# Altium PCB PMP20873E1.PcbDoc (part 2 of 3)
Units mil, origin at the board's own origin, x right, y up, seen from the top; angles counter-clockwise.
Board outline 7700 x 3300 mil, 6 copper layers (Layer 1 - Top Layer, Layer 2 - Inner Signal 1, Layer 3 - Inner Signal 2, Layer 4 - Inner Signal 3, Layer 5 - Inner Signal 4, Layer 6 - Bottom Layer), stack 64 mil thick; 258 components, 121 nets, 676 pads, 168 vias.
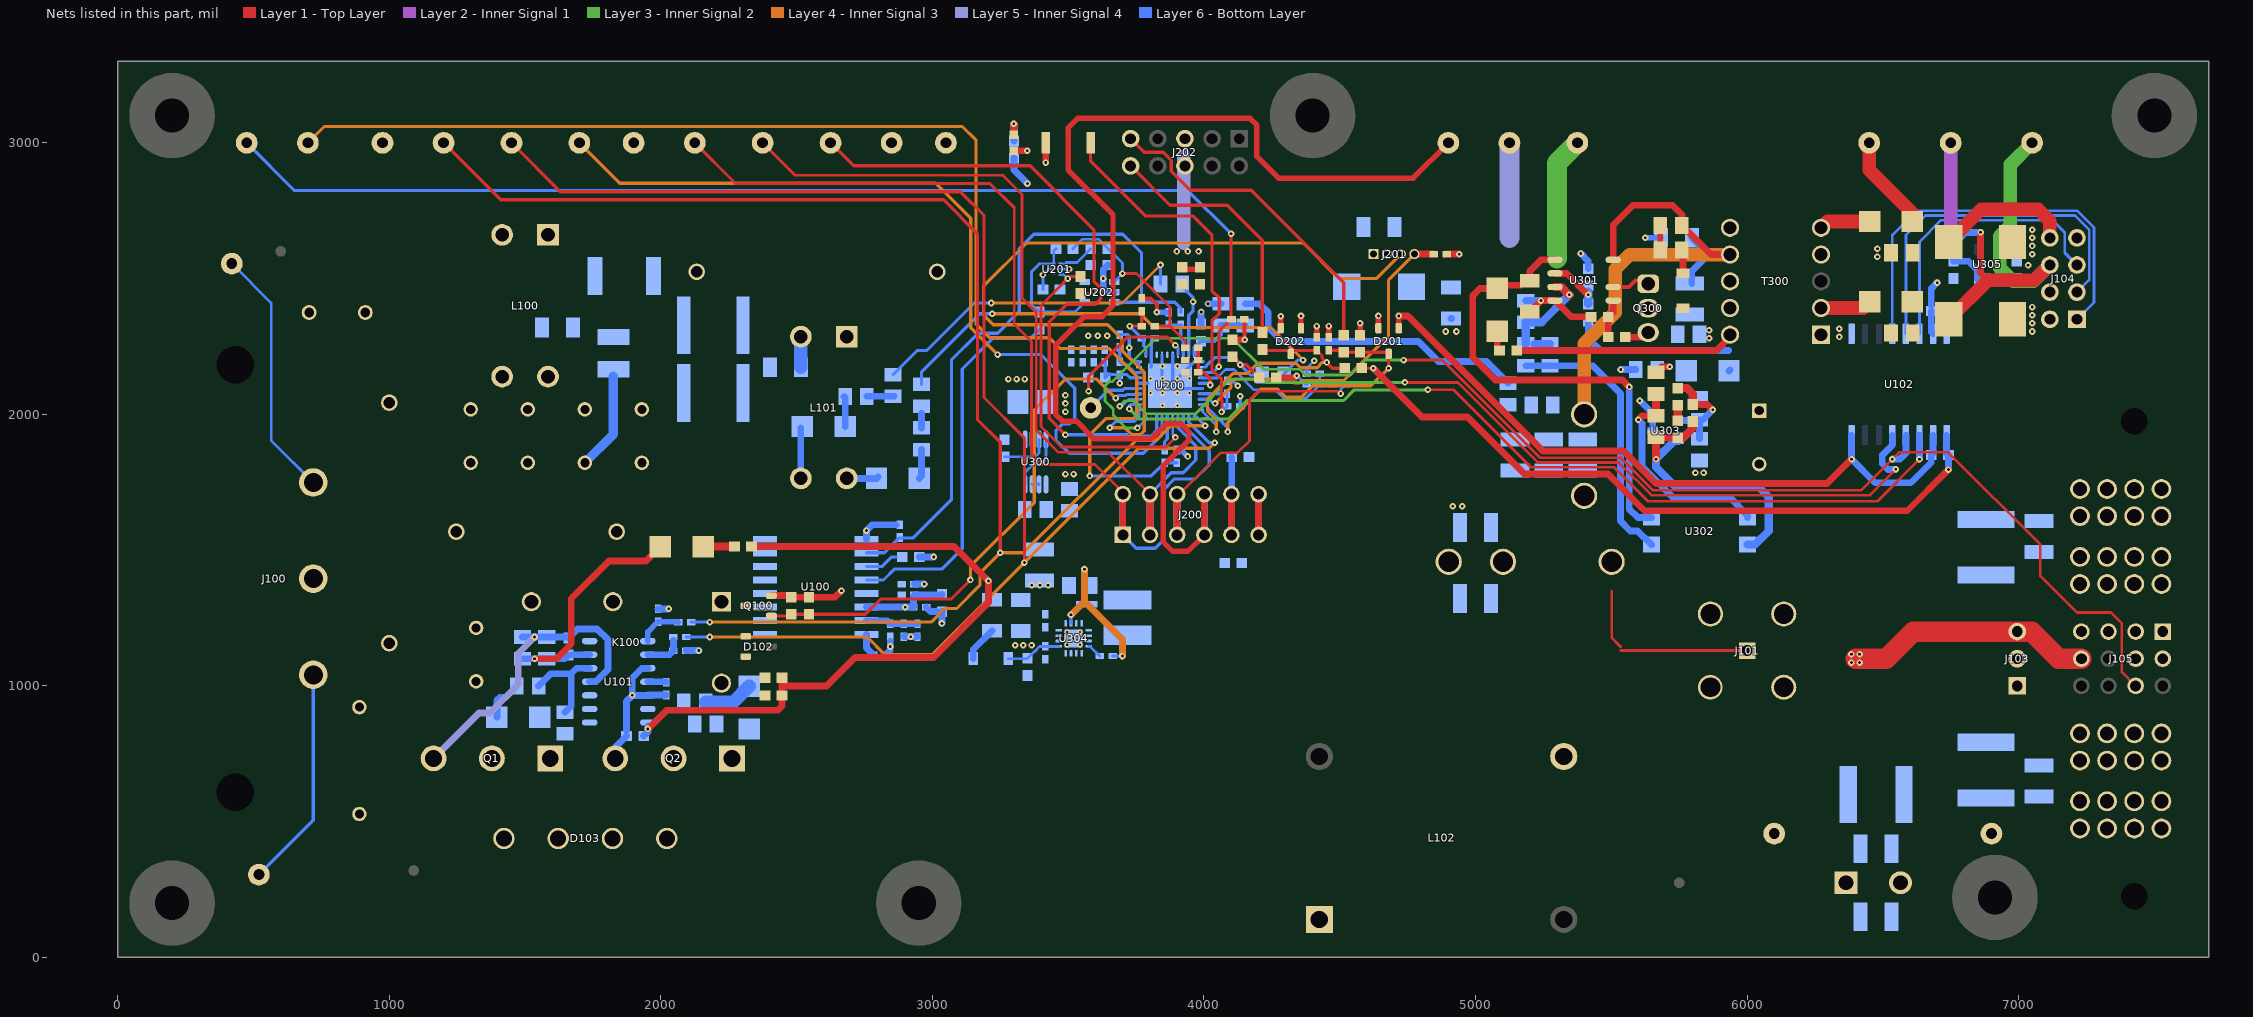
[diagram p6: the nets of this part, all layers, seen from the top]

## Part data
C100 C101 C104 C105: "CAP, CERM, 2200pF, 250V, +/-20%, KY, Radial D8x5mm"
C102: "CAP, Film, 0.47 µF, 275 V, +/- 20%, TH"
C103: library part ECQ-U2A474ML, "CAP, Film, 1uF, 275V, +/-20%, TH"
C107: "CAP, Film, 1 µF, 450 V, +/- 5%, TH"
C108 C109 C129 C130 C131 C132 C136 C137 C138: "CAP, CERM, 0.047 µF, 630 V, +/- 10%, X7R, 1210"
C110: library part DE1E3KX222MA4BL01, "CAP, CERM, 2200pF, 250V, +/-20%, E, Cap, 7x12x9 mm TH"
C111 C112: "CAP, CERM, 10uF, 16V, +/-20%, X5R, 0805"
C113 C126 C127 C222 C224 C320 C322: "CAP, CERM, 1uF, 25V, +/-10%, X7R, 0603"
C114 C122 C123: "CAP, CERM, 0.1uF, 6.3V, +/-10%, X7R, 0402"
C115: "CAP, CERM, 0.01uF, 50V, +/-10%, X7R, 0603"
C116: "CAP, CERM, 1000pF, 50V, +/-10%, X7R, 0603"
C117: "CAP, CERM, 1uF, 6.3V, +/-10%, X5R, 0603"
C118: "CAP, CERM, 0.022uF, 6.3V, +/-10%, X7R, 0402"
C119: "CAP, CERM, 1000pF, 50V, +/-10%, X7R, 0402"
C120 C121: "CAP, CERM, 1000pF, 6.3V, +/-10%, X5R, 0402"
C124 C125: "CAP, CERM, 0.056 µF, 250 V, +/- 10%, X7R, 2220"
C133 C134 C135: "CAP, CERM, 0.22 µF, 630 V, +/- 10%, X7R, 2220"
C188: "CAP, CERM, 1000pF, 16V, +/-10%, X7R, 0603"
C200 C203 C206 C219 C220: "CAP, CERM, 0.1uF, 6.3V, +/-10%, X5R, 0402"
C201: "CAP, CERM, 1000pF, 10V, +/-10%, X5R, 0402"
C202 C205: "CAP, CERM, 0.01uF, 6.3V, +/-10%, X7R, 0402"
C204: "CAP, CERM, 4700pF, 6.3V, +/-10%, X5R, 0402"
C207 C223: "CAP, CERM, 0.1 µF, 50 V, +/- 10%, X7R, 0603"
C208 C218: "CAP, CERM, 2.2uF, 10V, +/-10%, X5R, 0402"
C209 C210: library part Capacitor, "CAP, CER, 4.7UF, 6.3V, 20%, X5R, 0402"
C211 C212: "CAP, CERM, 2200 pF, 50 V, +/- 10%, X7R, 0603"
C213: "CAP, CERM, 1uF, 10V, +/-10%, X5R, 0402"
C214 C215: "CAP, CERM, 100pF, 50V, +/-5%, C0G/NP0, 0402"
C216 C217: "CAP, CERM, 1 µF, 25 V, +/- 10%, X7R, 0603"
C221: "CAP, TA, 100 µF, 16 V, +/- 10%, 0.1 ohm, SMD"
C288: "CAP, CERM, 2.2 µF, 25 V, +/- 10%, X5R, 1206"
C300: "CAP, CERM, 0.033 µF, 630 V, +/- 10%, X7R, 1210"
C301: "CAP, CERM, 1000 pF, 250 V, +/- 10%, X7R, 0805"
C303: "CAP, AL, 330 µF, 25 V, +/- 20%, 0.053 ohm, TH"
C304 C306 C323: "CAP, CERM, 3.3uF, 25V, +/-10%, X7R, 0805"
C305: "CAP, TA, 4.7uF, 10V, +/-10%, 3.4 ohm, SMD"
C307 C308: "CAP, CERM, 10 µF, 10 V, +/- 10%, X5R, 0805"
C309: "CAP, CERM, 0.047 µF, 50 V, +/- 10%, X7R, 0805"
C310: "CAP, CERM, 10 µF, 25 V, +/- 10%, X7R, 1206"
C311: "CAP, CERM, 68pF, 50V, +/-5%, C0G/NP0, 0603"
C312: "CAP, CERM, 1000pF, 50V, +/-10%, C0G/NP0, 0603"
C313: "CAP, CERM, 0.022uF, 25V, +/-10%, X7R, 0603"
C314 C321: "CAP, TA, 220 µF, 16 V, +/- 10%, 0.05 ohm, SMD"
C315 C326: "CAP, CERM, 22 µF, 16 V, +/- 20%, X5R, 1206"
C316 C317: "CAP, CERM, 0.1uF, 50V, +/-10%, C0G/NP0, 0402"
C318: "CAP, CERM, 10uF, 10V, +/-10%, X7R, 0805"
C319: "CAP, CERM, 2200pF, 25V, +10/%, X7R, 0402"
C324: "CAP, CERM, 47 µF, 6.3 V, +/- 20%, X5R, 1210"
D100 D101: "Diode, Fast Rectifier, 800 V, 1 A, SMA"
D102 D201 D202: "Diode, Schottky, 30V, 0.2A, SOT-23"
D103: "Diode, Switching-Bridge, 420V, 8A, TH"
D106: "Diode, Ultrafast, 600V, 1A, SMA"
D107 D108: "Diode, Schottky, 30 V, 1 A, SMA"
D300 D302 D304: library part 10BQ100TRPBF, "Diode, Schottky, 100V, 1A, SMB"
D301: library part US1M-13-F, "Diode, Ultrafast, 800V, 1A, SMA"
D303: "Diode, Ultrafast, 200 V, 1 A, SMA"
D305: "LED, Green, SMD"
D306: "Diode, Zener, 9.1 V, 500 mW, SOD-123"
F100: "Fuse, 15 A, 250 V, TH"
FID1 FID2 FID3: "Fiducial mark.  There is nothing to buy or mount."
H1 H2 H3 H4 H9 H11: "Machine Screw, Round, #4-40 x 1/4, Nylon, Philips panhead"
H5 H6 H7 H8 H10 H12: "Standoff, Hex, 0.5\"L #4-40 Nylon"
J100: "AC Receptacle, 10A 250VAC"
J101: "50 OHM BNC ELEVATED STRAIGHT JACK, TH"
J102: "Terminal Block, 2x1, 5.08mm, TH"
J103: "Header, 100mil, 3x1, Gold, TH"
J104: "Header, 100mil, 4x2, Gold, TH"
J105: "Signal Power Combo Socket Strip, 4x3, 4 Power Group, R/A, Gold, TH"
J106 J107 J203 J204 J205: library part 0312-0-15-15-34-27-10-0, "Pin Receptacle, .032-.046\" .075\" Dia, Gold, TH"
J200: "Receptacle, 2.54mm, 6x1, Gold, TH"
J201: "SOCKET .050\" GRID SIP 4 POS R/A, TH"
J202: "Header, 100mil, 5x2, Gold, TH"
K100: "Relay, SPST-NO (1 Form A), 10 A, 12 VDC, TH"
L100 L101: "Coupled inductor, 1.68 mH,  A,  ohm, TH"
L102: "Inductor, Toroid, Ferrite, 327 µH, 0.065 ohm, TH"
L103: "Inductor, Wirewound, 10 mH, 0.02 A, 32.8 ohm, SMD"
L104: "Inductor, Wirewound, Ferrite, 1.5 mH, 0.04 A, 37 ohm, SMD"
L300: "Inductor, Drum Core, Ferrite, 2.2 µH, 2.6 A, 0.047 ohm, SMD"
LBL1: library part THT-13-457-10, "Thermal Transfer Printable Labels, 1.250\" W x 0.250\" H - 10,000 per roll"
Logo2: library part Pb-Free
Logo3: library part FCC_disclaimer, "FCC_disclaimer"
LOGO4: library part IEC_HighVoltage, "IEC 61010-1 High Voltage Warning"
LOGO5: library part IEC_HotSurface, "IEC 61010-1 Hot Surface Warning"
NT200: "Single point connection between nets."
Q1 Q2: "MOSFET, N-CH, 500 V, 110 A, TO-247"
Q100: "MOSFET, N-CH, 60V, 0.26A, SOT-23"
Q300: "MOSFET, N-CH, 800V, 2.5A, IPAK"
R100 R101 R102 R103 R104 R105 R205 R209 R211: "RES, 348k ohm, 0.1%, 0.125W, 0805"
R106 R107: "RES, 51.1 ohm, 1%, 0.1W, 0603"
R108: "RES, 10.0k ohm, 1%, 0.1W, 0603"
R109 R110: "RES, 4.99 k, 1%, 0.125 W, 0805"
R112: "RES, 10.0k ohm, 1%, 0.063W, 0402"
R113: "RES, 12.7k ohm, 1%, 0.063W, 0402"
R114: "RES, 200 ohm, 1%, 0.1W, 0603"
R115: "RES, 5.49k ohm, 1%, 0.063W, 0402"
R116: "RES, 330k ohm, 5%, 0.063W, 0402"
R117 R118: "RES, 1.0k ohm, 5%, 0.063W, 0402"
R119 R120: "RES, 10.0, 1%, 0.125 W, 0805"
R121: "RES, 2.00 k, 1%, 0.25 W, 1206"
R122: "RES, 100, 1%, 0.25 W, 1206"
R202: "RES, 10.0 k, 1%, 0.1 W, 0402"
R203: "RES, 2.0k ohm, 5%, 0.063W, 0402"
R204: "RES, 3.3k ohm, 5%, 0.063W, 0402"
R206: "RES, 3.09 k, 0.1%, 0.062 W, AEC-Q200 Grade 0, 0402"
R207: "RES, 1.40k ohm, 1%, 0.063W, 0402"
R208 R218 R219 R220 R302: "RES, 2.0k ohm, 5%, 0.1W, 0603"
R212 R215: "RES, 10k ohm, 5%, 0.063W, 0402"
R213: "RES, 5.11k ohm, 0.1%, 0.125W, 0805"
R214: "RES, 1.00 ohm, 1%, 0.1W, 0603"
R216 R217: "RES, 5.11 k, 0.1%, 0.1 W, 0603"
R221 R223: "RES, 100 ohm, 5%, 0.1W, 0603"
R222: "RES, 221, 1%, 0.063 W, 0402"
R224: "RES, 10.0, 1%, 0.25 W, 1206"
R225: "RES, 1.00 k, 1%, 0.1 W, 0603"
R226: "RES, 4.87 k, 0.1%, 0.062 W, AEC-Q200 Grade 0, 0402"
R300: "RES, 300 k, 1%, 0.25 W, 1206"
R301: "RES, 200, 5%, 0.125 W, 0805"
R303: "RES, 100k ohm, 1%, 0.063W, 0402"
R304: "RES, 330 k, 0.1%, 0.1 W, 0603"
R305: "RES, 750, 0.5%, 0.1 W, 0603"
R307: "RES, 20.0, 1%, 0.1 W, 0603"
R308: "RES, 60.4k ohm, 1%, 0.1W, 0603"
R309: "RES, 3.01 k, 1%, 0.125 W, 0805"
R310: "RES, 22.1 k, 1%, 0.125 W, 0805"
R311 R315: "RES, 1.00k ohm, 1%, 0.1W, 0603"
R312: "RES, 21.5k ohm, 1%, 0.1W, 0603"
R313: "RES, 2.00 k, 1%, 0.125 W, 0805"
R314: "RES, 0.91, 1%, 0.25 W, 0805"
R316: "RES, 12.1 k, 1%, 0.125 W, 0805"
R317: "RES, 1.24 k, 1%, 0.125 W, 0805"
R318: "RES, 196 k, 1%, 0.125 W, 0805"
RT100: "Thermistor NTC, 50 ohm, 25%, D12.5xH16.5mm"
S200: "Switch, Push Button, SMD"
T300: "Transformer, 13 mH, TH"
TP100 TP109 TP300 TP301 TP302 TP303 TP304: library part 5000, "Test Point, Miniature, Red, TH"
TP102 TP103 TP108 TP205 TP206 TP212 TP305: library part 5001, "Test Point, Miniature, Black, TH"
TP200 TP201 TP202 TP203 TP204 TP207 TP208 TP209 TP210: library part 5002, "Test Point, Miniature, White, TH"
U100: "120 kHz Bandwidth, High-Voltage Isolation Current Sensor with Integrated Overcurrent Detection"
U101: "High-Speed,4A, 600V High-side Low-side Gate Driver Device, D0014A"
U102: "High-Performance, 8000 VPK Reinforced Triple Digital Isolator, DW0016B"
U200: "Highly Integrated Digital Controller for Isolated Power, RHA0040B"
U201: "SINGLE-POLE DOUBLE-THROW ANALOG SWITCH, DRY0006A"
U202: "Precision, Low Noise, Low Iq Operational Amplifier, 2.2 to 5.5 V, -40 to 125 degC, 5-pin SOT23 (DBV0005A), Green (RoHS & no Sb/Br)"
U300: "Micropower, 200 mA Ultra Low-Dropout Fixed or Adjustable Voltage Regulator, 8-pin Mini SOIC"
U301: "Constant-Voltage, Constant-Current Flyback Controller Using Opto-Coupler Feedback, D0007A"
U302: "Optocoupler, 5 kV, 50-600% CTR, TH-4"
U303: "Low Voltage Adjustable Precision Shunt Regulator, 39 ppm / degC, 15 mA, 0 to 70 degC, 3-pin SOT-23 (DBZ), Green (RoHS & no Sb/Br)"
U304: "Buck Step Down Regulator with 3 to 17 V Input and 5 V Output, -40 to 85 degC, 16-Pin QFN (RGT), Green (RoHS & no Sb/Br)"
U305: "Single Output LDO, 150 mA, Fixed 3.3 V Output, 2.5 to 24 V Input, with Ultra-Low IQ, 5-pin SOT-23 (DBV), -40 to 85 degC, Green (RoHS & no Sb/Br)"
ZZ1: library part AssemblyNoteLabel
ZZ2 ZZ3 ZZ4: library part AssemblyNote

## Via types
v1: diameter 24, hole 10, Layer 1 - Top Layer to Layer 6 - Bottom Layer, 148 vias
v2: diameter 19.68, hole 7.87, Layer 1 - Top Layer to Layer 6 - Bottom Layer, 12 vias
v3: diameter 19.68, hole 7.87, Layer 1 - Top Layer to Layer 6 - Bottom Layer, tented top, 5 vias
v4: diameter 20, hole 12, Layer 1 - Top Layer to Layer 6 - Bottom Layer, 2 vias
v5: diameter 90.55, hole 72.83, Layer 1 - Top Layer to Layer 6 - Bottom Layer, 1 vias

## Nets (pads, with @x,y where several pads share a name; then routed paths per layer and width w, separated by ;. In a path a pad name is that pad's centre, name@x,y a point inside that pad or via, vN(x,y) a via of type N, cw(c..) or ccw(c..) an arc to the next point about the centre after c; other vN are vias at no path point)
3V3: C117.1 C123.1 C126.2 C208.1 C209.1 C219.1 C222.2 C224.2 C305.1 D201.2 D202.2 J202.5 R112.2 R113.2 R116.1 R202.2 R214.2 R219.2 R220.2 R222.2 R304.2 R305.2 TP301.1 U100.14 U102.1 U200.27 U201.5 U202.5 U300.5 U300.6 | length 3564.5
  Layer 1 - Top Layer w10: R220.2@4581.5,2170 v1(4623,2170)
  Layer 1 - Top Layer w20: D202.2@4282.6,2307.4 v1@4282.6,2361 ; R219.2@4575,2291.5 v1(4575,2335) ; D201.2@4642.6,2307.4 v1(4642.6,2362.4)
  Layer 1 - Top Layer w25: v1(4623,2170) 4803,1990 4970,1990 5180,1780 5488.08,1780 5623.08,1645 6590,1645 v1(6741.5,1796.5)
  Layer 6 - Bottom Layer w10: U201.5@3470.31,2534.93 v1(3503.5,2534.93) ; R202.2@4379.38,2150 4379.38,2170.38 v1(4406,2197)
  Layer 6 - Bottom Layer w12: C209.1@3635,2191.38 3636.5,2189.88 R214.2@3636.5,2135 3647.87,2146.38 C208.1@3690,2146.38 ; v1(3690,2114) C208.1@3690,2146.38 ; U200.27@3760.83,2134.53 3728.47,2134.53 3716.62,2146.38 C208.1@3690,2146.38 ; R222.2@4133.62,2030 v1(4133.62,2066.38)
  Layer 6 - Bottom Layer w25: U100.14@2757.01,1290 C123.1@2930,1290 2930,1331.38 R116.1@2933.62,1335 3033.5,1335 C117.1@3035,1336.5 ; R112.2@2828.62,1115 2845,1131.38 2845,1164.63 ; R305.2@3300,2943.5 3300,2900 v1(3350,2850) ; U102.1@6735,1922.99 6735,1856.5 C126.2@6741.5,1850 v1(6741.5,1796.5)
  other v1: 2845,1145 2900,1290 3280,2130 3310,2130 3340,2130 4283,2361
3V3LLC: C127.2 C322.2 J104.4 U102.16 U305.1 | length 9.2
  Layer 6 - Bottom Layer w25: C127.2@6735,2373.5 C127.2@6741.5,2380
5V: C216.2 C307.1 C308.1 C317.1 C318.2 C324.1 J200.4 L300.2 R303.2 TP304.1 U300.4 U300.8 U304.14 | length 5105.2
  Layer 1 - Top Layer w20: J200.4@4001.3,1556.05 3941.03,1495.78 3885,1495.78 3850,1530.78 3850,1810 3945,1905 3945,1935 3915,1965 3860,1965 3805,1910 3595,1910 3530,1975 3478.5,1975 3453.5,2000 3453.5,2253.5 3560,2360 3625,2360 3665,2400 3665,2735 3500,2900 3500,3055 3535,3090 4170,3090 4195,3065 4195,2950 4275,2870 4770,2870 TP304.1@4900,3000
  Layer 1 - Top Layer w25: J200.4@4001.3,1556.05 J200.4@4001.3,1706.05
  Layer 4 - Inner Signal 3 w25: v1(3510.31,1261.69) 3560,1311.37 ; v1(3560,1430) 3560,1311.37 ; v1(3700,1110) 3700,1171.37 3560,1311.37
  Layer 6 - Bottom Layer w10: U300.4@3341.61,1742.32 3341.61,1786.61 3370,1815 3400,1815 3418.39,1833.39 U300.8@3418.39,1907.68 ; U304.14@3510.31,1230 v1(3510.31,1261.69) ; R303.2@3663.62,1110 v1(3700,1110)
  Layer 6 - Bottom Layer w25: J200.4@4001.3,1556.05 J200.4@4001.3,1706.05
7VLLC: C304.1 C314.1 C320.2 D304.1 J104.6 TP302.1 U305.3 | length 1696.5
  Layer 1 - Top Layer w25: v1(6860,2670) 6860,2520.87 6886.87,2494
  Layer 1 - Top Layer w50: C314.1@6742.87,2350 6886.87,2494 7059,2494 J104.6@7115,2550
  Layer 3 - Inner Signal 2 w50: TP302.1@7050,3000 6970,2920 6970,2695 6930,2655 6930,2540 6980,2490 7055,2490 J104.6@7115,2550
  Layer 6 - Bottom Layer w25: U305.3@6847.6,2498.87 6847.6,2532.4 6816.5,2563.5 C320.2@6760,2563.5 6760,2625 6805,2670 v1(6860,2670)
10VLLC: C306.1 C321.1 D302.1 J104.8 TP303.1 | length 857.4
  Layer 1 - Top Layer w50: TP303.1@6450,3000 6450,2900 6608.74,2741.26 D302.1@6608.74,2710 ; C321.1@6742.87,2635 6862.87,2755 7072,2755 7115,2712 J104.8@7115,2650
12V: C115.1 C217.2 C303.1 C315.1 C316.1 C323.1 C326.1 D300.1 D306.1 J103.3 J105.8 J200.5 R106.2 R107.2 R114.2 R224.2 R309.2 R316.2 TP300.1 U101.7 U304.10 U304.11 U304.12 U304.13 | length 4567.8
  Layer 1 - Top Layer w25: v1(1952.28,841.37) 2020.91,910 2430,910 2446.5,926.5 R106.2@2446.5,965 2446.5,1000 ; R114.2@2333.99,1513 3079.99,1513 v1(3206.5,1386.5) 3206.5,1306.5 3005,1105 2715,1105 2610,1000 2446.5,1000 ; R107.2@2446.5,1030 2446.5,1000 ; J200.5@4101.3,1556.05 J200.5@4101.3,1706.05 ; R309.2@5665,2155 5685,2175 v1(5715,2175)
  Layer 1 - Top Layer w75: 6400.26,1100 6512.52,1100 6612.52,1200 J103.3@6995,1200 7048.03,1200 7148.03,1100 J105.8@7231,1100
  Layer 3 - Inner Signal 2 w75: 5300,2575 5300,2925 TP300.1@5375,3000
  Layer 6 - Bottom Layer w25: C115.1@1936.5,815 1952.28,830.79 v1(1952.28,841.37) v1@1952.28,851.96 ; D306.1@3150.53,1100 3150.53,1133.44 C326.1@3220,1202.91 ; J200.5@4101.3,1556.05 J200.5@4101.3,1706.05 4102.6,1707.35 C217.2@4102.6,1843.35 ; R224.2@4910,2352.91 R224.2@4912,2352.91
  other v1: 6384.26,1086 6414.26,1086 6384.26,1116 6414.26,1116 3305,1150 3335,1150 3365,1150 4890,2305 4930,2305
+BRDG_N: R109.2 R119.2 U101.12 | length 366.2
  Layer 6 - Bottom Layer w25: R119.2@1550,1000 1595,1045 1670,1045 ; R109.2@1647,903 1670,926 1670,1045 ; U101.12@1737.72,1065 1690,1065 1670,1045
+BRDG_P: R110.2 R120.2 U101.6
-BRDG_N: C111.2 C112.2 C113.1 D103.3 Q1.3 Q2.2 U100.1 U100.2 U100.3 U100.4 U101.11 | length 1167.2
  Layer 5 - Inner Signal 4 w25: Q1.3@1163,733 1330,900 1370,900 1475,1005 1475,1120 v1(1535,1180)
  Layer 6 - Bottom Layer w25: C111.2@1490,1180 v1(1535,1180) C112.2@1580,1180 1656.5,1180 C113.1@1660,1176.5 1693.5,1210 1765,1210 1805,1170 1805,1060.21 1759.79,1015 U101.11@1737.72,1015
"\RECTIFIER SHTDWN": C122.1 U101.4 | length 68.3
  Layer 6 - Bottom Layer w25: U101.4@1952.28,1015 2018.62,1015 C122.1@2020,1013.62
AC_CUR_FAULT: C118.2 R116.2 U100.13
AC_CUR_SENSE: R225.1 U100.12 | length 1408.3
  Layer 6 - Bottom Layer w12: U100.12@2757.01,1390 2820,1390 2860,1430 3035,1430 3110,1505 3110,2167 3222.5,2279.5 3248.08,2279.5 3248.58,2280 3361.5,2280 R225.1@3395,2313.5
AC_CUR_VREF: C121.1 R212.2 U100.10 U202.3 | length 2415.7
  Layer 6 - Bottom Layer w12: U100.10@2757.01,1490 2823.62,1490 2878.62,1545 2930,1545 3070,1685 3070,2200 3169,2299 3240,2299 3320,2379 3320,2610 3373.5,2663.5 3701.5,2663.5 3770,2595 3770,2412.6 ; U202.3@3669.13,2412.6 3770,2412.6 ; R212.2@3915,2376.34 3915,2390 3892.4,2412.6 3770,2412.6
AC_DROP: TP210.1 U200.25 | length 207.3
  Layer 6 - Bottom Layer w12: TP210.1@3583,2024 3647.5,2088.5 3700.56,2088.5 3707.22,2095.16 U200.25@3760.83,2095.16
AC_L: C107.1 D103.2 K100.3 L102.1 RT100.2
AC_N: C105.2 C107.2 D101.2 L101.3 U100.5 U100.6 U100.7 U100.8 | length 185.2
  Layer 6 - Bottom Layer w25: L101.3@2515.5,1764 D101.2@2515.5,1949.24
ACL_SENSE: C212.1 R102.1 R217.2 U200.2 | length 399.1
  Layer 1 - Top Layer w12: C212.1@4105,2223.5 C212.1@4105,2212 v1(4134,2183) 4155.5,2183 R217.2@4203.5,2135
  Layer 6 - Bottom Layer w12: 4003.08,2174.08 4005.08,2174.08 4016.5,2185.51 4016.5,2186.5 4039,2209 4111,2209 v1@4135,2185 ; v1@4133,2182 4170,2145 R102.1@4215,2145 ; v1@4133,2183 v1@4133,2186
ACN_SENSE: C211.1 R105.1 R216.2 U200.39 | length 298.2
  Layer 6 - Bottom Layer w12: R105.1@3910,2490 3910,2480 3960,2430 v1(3960,2415) 3960,2381.1 3943.9,2365 U200.39@3943.9,2219.17
AGND: C114.2 C116.2 C117.2 C118.1 C121.2 C123.2 C126.1 C200.1 C201.2 C202.1 C203.2 C204.2 C205.2 C206.1 C207.2 C209.2 C210.2 C211.2 C212.2 C213.2 C214.2 C215.2 C218.2 C219.2 C220.2 C222.1 C223.2 C224.1 C305.2 C307.2 C308.2 D201.1 D202.1 D305.2 J202.6 NT200.2 R115.1 R213.1 R216.1 R217.1 R226.1 S200.2 TP205.1 TP206.1 TP212.1 U100.9 U102.2 U102.8 U200.1 U200.6 U200.26 U200.29 U200.30 U200.32 U200.34 U200.36 U200.41 U201.2 U202.2 U300.1 | length 5238.4
  Layer 1 - Top Layer w10: C223.2@3544.93,2444.82 3584.44,2444.82 v1(3592.31,2452.69)
  Layer 1 - Top Layer w15: R226.1@3771.38,2427.24 3802.76,2427.24 3826.38,2403.62 v1(3826.38,2376.34) ; v1@4148.62,2276.36 C200.1@4148.62,2350
  Layer 1 - Top Layer w20: R216.1@3920,2550 3936.38,2533.62 C211.2@3985,2533.62 ; D202.1@4357.4,2307.4 v1(4357.4,2362.4) ; C214.2@4415,2283.62 v1(4415,2325) ; C215.2@4460,2283.62 v1(4460,2325) ; D201.1@4717.4,2307.4 D201.1@4717.4,2317.24 v1(4717.4,2362.4)
  Layer 1 - Top Layer w25: D305.2@3300,2970.47 v1(3349.53,2970.47) ; v1(3417.32,2927.32) S200.2@3417.32,3000 ; C212.2@4105,2274.99 v1(4150,2275) ; R217.1@4266.5,2135 4335.29,2135 v1@4341.79,2141.5 ; v1(4717.4,2362.4) 4750.64,2362.4 5248.04,1865 5545,1865 5665,1745 6295,1745 v1(6385,1835)
  Layer 5 - Inner Signal 4 w50: 3925,2630 3925,2950
  Layer 6 - Bottom Layer w10: C222.1@3407.01,2460 v1(3407.01,2513.44) 3428.5,2534.93 3439.79,2534.93 ; v1(4342,2142) 4374,2110 C201.2@4379.38,2110
  Layer 6 - Bottom Layer w12: C213.2@3690,2293.62 3719.38,2293.62 3725,2288 3725,2210 3741.42,2193.58 U200.30@3760.83,2193.58 U200.29@3760.83,2176 ; U200.26@3755,2114.84 U200.41@3794.29,2114.84 ; U200.41@3806.1,2173.9 U200.32@3806.1,2219.17 3806.1,2267.48 C204.2@3818.62,2280 ; U200.41@3845.47,2134.53 U200.34@3845.47,2219.17 ; U200.41@3875,2105 U200.41@3884.84,2114.84 ; U200.41@3884.84,2095.16 U200.6@3995,2095.16 ; U200.36@3884.84,2219.17 U200.41@3884.84,2114.84 ; U200.1@3997,2193.58 3963.58,2193.58 U200.41@3884.84,2114.84 ; C218.2@4085,2123.62 4106.38,2123.62 v1(4125,2105)
  Layer 6 - Bottom Layer w20: v1(3826.38,2376.34) C206.1@3870,2376.34 ; C202.1@3900,1868.62 3903.62,1865 3920,1865 v1(3940,1845)
  Layer 6 - Bottom Layer w25: U100.9@2757.01,1540 v1(2757.01,1572.01) 2778.62,1593.62 2867.19,1593.62 ; R115.1@2895,1181.38 C114.2@2945,1181.38 ; C118.1@2933.62,1375 v1(2970,1375) ; C116.2@2951.5,1475 v1(3005,1475) ; C123.2@2977.24,1290 2993.74,1273.5 3015.3,1273.5 ; v1(3035,1230) C117.2@3035,1273.5 ; C224.1@3646.5,2550 3629.45,2532.95 3629.45,2465.55 3645,2450 U202.2@3669.13,2450 ; C207.2@3989,2332.5 3989,2376 v4(3990,2377) ; v4(4015,2407) R213.1@4063,2407 ; U102.8@6385,1922.99 v1(6385,1835) 6471.97,1748.03 6603.03,1748.03 6678.5,1823.5 C126.1@6678.5,1850 6685,1856.5 U102.2@6685,1922.99
  other v1: 2920,1181.38 3490,1780 3520,1780 3490,2010 3490,2040 3490,2070 3725,2245 3574,2289 3609,2289 3644,2289 3629.45,2500 3900,2600 3940,2600 3980,2600
  other v2: 3848.03,2033.15 3901.97,2033.15 3803.15,2078.03 3848.03,2078.03 3901.97,2078.03 3946.85,2078.03 3803.15,2131.97 3848.03,2131.97 3901.97,2131.97 3946.85,2131.97 3848.03,2176.85 3901.97,2176.85
CT1: T300.8
EAP1: U200.33
EAP2: U200.35
EARTH: C100.2 C101.2 C104.1 C105.1 C110.1 J100.3
FAN_CTRL: J201.4 R215.2 U200.8 | length 1239.4
  Layer 1 - Top Layer w25: J201.4@4775,2590 R215.2@4846.38,2590
  Layer 4 - Inner Signal 3 w12: v1(4041,2040) 4099.5,2098.5 4099.5,2115.56 4114.44,2130.5 4317.44,2130.5 4331.44,2116.5 4352.56,2116.5 4360.56,2124.5 4514.5,2124.5 4680,2290 4680,2495 J201.4@4775,2590
  Layer 6 - Bottom Layer w12: U200.8@3983,2055.79 4019.21,2055.79 4035,2040 v1(4041,2040)
FAN_FB: J201.3 U200.21 | length 3013
  Layer 4 - Inner Signal 3 w12: v1(3653,1951) 3708.5,1951 3735,1924.5 3765.56,1924.5 3780.5,1939.44 3780.5,2067.67 3779.81,2068.36 3779.81,2154.13 3699.5,2234.44 3699.5,2275.5 3645,2330 3223.94,2330 3188,2365.94 3188,2472 3347,2631 4365,2631 4496,2500 4635,2500 J201.3@4725,2590
  Layer 6 - Bottom Layer w12: v1@3651.24,1951 v1(3653,1951) 3675.62,1973.62 3742.56,1973.62 3744.44,1975.5 3745.5,1975.5 3760.83,1990.83 U200.21@3760.83,2014
G_AC_I: C223.1 U200.15 U201.6 | length 1290.6
  Layer 1 - Top Layer w10: C223.1@3544.93,2507.81 3506.38,2507.81 v1(3498.5,2499.93) 3400.01,2401.44 3400.01,1954.99 3475,1880 3860,1880 v1(3895,1915)
  Layer 6 - Bottom Layer w10: U201.6@3470.31,2515.25 3483.19,2515.25 v1(3498.5,2499.93) ; U200.15@3884.84,1990.83 3884.84,1925.16 v1(3895,1915)
GAN_FAULT: C201.1 R202.1 R203.1 U200.4 | length 601.6
  Layer 6 - Bottom Layer w10: U200.4@3989.17,2134.53 3989.7,2134 4048.65,2134 4079.65,2165 4110,2165 4185,2090 4264,2090 4293,2061 4377.62,2061 C201.1@4426.62,2110 ; R202.1@4426.62,2150 C201.1@4426.62,2110 ; R203.1@4474.38,2110 C201.1@4426.62,2110
HS_GATE1: J200.1 TP202.1 U200.13 | length 3704.8
  Layer 1 - Top Layer w10: 3301,2760 3301,2332 3365.01,2267.99 3365.01,1854.99 3405,1815 3599,1815 3701.3,1712.7 J200.1@3701.3,1706.05
  Layer 1 - Top Layer w12: TP202.1@2125,3000 2275,2850 3211,2850 3301,2760
  Layer 1 - Top Layer w25: J200.1@3701.3,1556.05 J200.1@3701.3,1706.05
  Layer 6 - Bottom Layer w12: J200.1@3701.3,1556.05 3750.3,1507.05 3820,1507.05 3850,1537.05 3850,1720.78 3891,1761.78 3967,1761.78 4020,1814.78 4020,1865 3924.21,1960.79 U200.13@3924.21,1997
  Layer 6 - Bottom Layer w25: J200.1@3701.3,1556.05 J200.1@3701.3,1706.05
HS_GATE2: TP209.1 U200.17 | length 3179.6
  Layer 4 - Inner Signal 3 w12: TP209.1@1700,3000 1849,2851 3012,2851 3141.5,2721.5 3141.5,2318.5 v1(3240,2220)
  Layer 6 - Bottom Layer w12: v1(3240,2220) 3400,2220 3524,2096 3524,1984 3505,1965 3480,1965 3455,1940 3455,1905 3503.74,1856.26 3776.26,1856.26 3845.47,1925.47 U200.17@3845.47,1990.83 U200.17@3845.47,1997
HVBUS: C108.1 C109.1 C129.1 C130.1 C131.1 C132.1 C133.2 C134.1 C135.2 C136.1 C137.1 C138.1 C300.1 C301.1 D103.1 J102.1 J105.P1 J105.P4 J106.1 J204.1 Q1.2 R205.2 R300.2 T300.7 TP100.1 U301.8 | length 1980.3
  Layer 1 - Top Layer w25: U301.8@5507.28,2569 5507.28,2697.28 5580,2770 5725,2770 5760,2735 5760,2727.5 ; C301.1@5760,2695 5866.57,2588.43 T300.7@5937.48,2588.43
  Layer 4 - Inner Signal 3 w50: J106.1@5400,2000 5400,2260 5515,2375 5515,2535 5568.43,2588.43 T300.7@5937.48,2588.43
  Layer 6 - Bottom Layer w25: C300.1@5796,2482.09 5796,2526 5858.43,2588.43 5858.66,2588.43 ; R300.2@5797.09,2650 5858.66,2588.43 ; T300.7@5937.48,2588.43 5858.66,2588.43
LLC_AGND: C127.1 C304.2 C306.2 C314.2 C320.1 C321.2 C322.1 J104.2 J104.7 T300.1 T300.4 TP305.1 U102.9 U102.15 U305.2 | length 479.9
  Layer 2 - Inner Signal 1 w50: 6750,2700 TP305.1@6750,3000
  Layer 6 - Bottom Layer w25: C127.1@6678.5,2380 6678.5,2303.5 U102.15@6685,2297.01 ; 6678.5,2399.7 6678.5,2463.5 v1(6700,2485)
  other v1: 6340,2285 7050,2305 6340,2315 7050,2335 7050,2365 7050,2395 7035,2548.72 6480,2580 7050,2590 6480,2610 7050,2620 7050,2650 7050,2680
LS_GATE1: J200.2 TP204.1 U200.14 | length 3152.8
  Layer 1 - Top Layer w10: TP204.1@2375,3000 2495,2880 3260,2880 3330,2810 3330,2427.51 3382.51,2375 3382.51,1942.49 3465,1860 3647.35,1860 J200.2@3801.3,1706.05
  Layer 1 - Top Layer w25: J200.2@3801.3,1556.05 J200.2@3801.3,1706.05
  Layer 6 - Bottom Layer w12: J200.2@3801.3,1706.05 3880.03,1784.78 3923,1784.78 3970,1831.78 3970,1885 3904.53,1950.47 U200.14@3904.53,1997
  Layer 6 - Bottom Layer w25: J200.2@3801.3,1556.05 J200.2@3801.3,1706.05
LS_GATE2: TP207.1 U200.18 | length 2436.8
  Layer 1 - Top Layer w12: TP207.1@2625,3000 2710,2915 3360,2915 3595,2680 3595,2490 3620,2465 3620,2425 3600,2405 3495,2405 3430,2340 3430,1985 v1(3490,1925)
  Layer 6 - Bottom Layer w12: v1(3490,1925) 3713.62,1925 3715,1926.38 3721.38,1920 3805,1920 3825.79,1940.79 U200.18@3825.79,1997
NCD1: U101.8
NCD2: U101.9
NCD3: U101.10
NCD4: U101.14
NetC100_1: C100.1 C103.1 L100.3 L101.1 L103.2 R121.1
NetC101_1: C101.1 D100.2 K100.2 L101.4 L104.2 RT100.1 | length 480.8
  Layer 6 - Bottom Layer w25: L101.4@2684.5,1764 D100.2@2794,1764 D100.2@2800,1770
  Layer 6 - Bottom Layer w35: C101.1@1720,1821.57 1825,1926.57 L104.2@1825,2140.94
NetC102_1: C102.1 F100.2 L100.2
NetC102_2: C102.2 J100.2 L100.1 TP108.1 | length 818.9
  Layer 6 - Bottom Layer w12: TP108.1@519.76,304.76 720,505 J100.2@720,1040.67
NetC103_2: C103.2 C104.2 L100.4 L101.2 R122.1 | length 112.6
  Layer 6 - Bottom Layer w50: R122.1@2515.5,2173.41 L101.2@2515.5,2286
NetC111_1: C111.1 C112.1 C113.2 D106.1 U101.13 | length 985.5
  Layer 1 - Top Layer w25: v1(1535,1100) 1615,1100 1670,1155 1670,1321 1809,1460 1945.26,1460 D106.1@1998.26,1513
  Layer 6 - Bottom Layer w25: C111.1@1490,1100 v1(1535,1100) C112.1@1580,1100 1646.5,1100 C113.2@1660,1113.5 1661.5,1115 U101.13@1737.72,1115
NetC114_1: C114.1 R113.1 R115.2 U100.15 | length 192.7
  Layer 6 - Bottom Layer w25: U100.15@2757.01,1240 2833.62,1240 R113.1@2845,1228.62 R115.2@2895,1228.62 C114.1@2945,1228.62
NetC116_1: C116.1 U100.11 | length 125.3
  Layer 6 - Bottom Layer w12: U100.11@2757.01,1440 2815,1440 2850,1475 2867.82,1475
NetC119_1: C119.1 R117.1 U101.1 | length 161.6
  Layer 6 - Bottom Layer w20: U101.1@1952.28,1165 1952.28,1198.66 C119.1@1990,1236.38 2062.62,1236.38 R117.1@2064,1235
NetC120_1: C120.1 R118.1 U101.2 | length 137.5
  Layer 6 - Bottom Layer w25: U101.2@1952.28,1115 2031.38,1115 C120.1@2046.38,1130 2046.38,1167.19
NetC124_1: C124.1 C125.1 L103.1
NetC124_2: C124.2 C125.2 R122.2
NetC202_2: C202.2 R204.2 TP203.1 | length 4695.4
  Layer 4 - Inner Signal 3 w12: TP203.1@700,3000 760,3060 3110,3060 3161,3009 3161,2332 3211,2282 3431,2282 3471,2242 3652,2242 3753,2141 3753,1997 3741,1985 3640,1985 3579,1924 v1(3579,1773)
  Layer 6 - Bottom Layer w12: v1(3579,1773) 3806.62,1773 R204.2@3855,1821.38 C202.2@3900,1821.38
NetC203_1: C203.1 C205.1 R207.1 U200.5 | length 214.7
  Layer 1 - Top Layer w12: R207.1@3978.62,2245 C205.1@3978.62,2200 C203.1@3978.62,2155 3999,2155 4023,2131 v1(4023,2108) v1@4020,2111
  Layer 6 - Bottom Layer w12: U200.5@3983,2114.84 U200.5@3989.17,2114.84 4017.16,2114.84 v1@4023.5,2108.5
NetC204_1: C204.1 R206.2 R226.2 U200.31 | length 238.8
  Layer 1 - Top Layer w12: v1(3726.38,2325) R206.2@3771.38,2325 R226.2@3771.38,2380 R226.2@3770,2381.38
  Layer 6 - Bottom Layer w12: v1(3726.38,2325) C204.1@3771.38,2280 3778,2273.38 3778,2253 3786.42,2244.58 U200.31@3786.42,2213
NetC206_2: C206.2 R212.1 U200.38 | length 162.4
  Layer 6 - Bottom Layer w12: C206.2@3870,2329.1 R212.1@3915,2329.1 ; R212.1@3918.62,2329.1 R212.1@3915,2329.1 ; U200.38@3924.21,2219.17 3924.21,2270.79 3915,2280 R212.1@3915,2329.1
NetC208_2: C208.2 C213.1 U200.28 | length 148.1
  Layer 6 - Bottom Layer w12: C213.1@3690,2248.37 C213.1@3690,2246.38 C208.2@3690,2193.62 3698.62,2185 3713,2185 3743.79,2154.21 U200.28@3767,2154.21
NetC210_1: C210.1 C220.1 R214.1 U200.37 | length 537.3
  Layer 1 - Top Layer w12: v1(3575,2085) 3575,2140 3720,2285 3864,2285 v1(3895,2254)
  Layer 6 - Bottom Layer w12: R214.1@3573.5,2135 3575,2133.5 v1(3575,2085) ; v1(3895,2254) 3904.53,2244.47 U200.37@3904.53,2219.17
NetC221_1: C221.1 C288.2 J201.2 R224.1
NetC301_2: C301.2 R300.1 R301.2 | length 152.9
  Layer 1 - Top Layer w20: R301.2@5680,2605 C301.2@5680,2695 C301.2@5680,2700
  Layer 6 - Bottom Layer w20: v1(5625,2650) R300.1@5682.91,2650
NetC309_1: C309.1 R318.2 U302.3 | length 1010.7
  Layer 6 - Bottom Layer w25: R318.2@5185,2179 C309.1@5275,2179 5431,2179 5533.5,2076.5 5533.5,1607.28 5569.92,1570.87 5596.97,1570.87 U302.3@5647.83,1520
NetC309_2: C309.2 R310.2 R318.1 U301.3 | length 403.6
  Layer 1 - Top Layer w30: U301.3@5292.72,2469 5316,2469 v1(5345,2440)
  Layer 6 - Bottom Layer w30: R318.1@5185,2259 R310.2@5185,2339 5244,2339 v1(5345,2440) ; 5217.5,2259 C309.2@5275,2259
NetC311_1: C311.1 R311.1 U301.5 | length 143.7
  Layer 1 - Top Layer w25: R311.1@5489.5,2284 R311.1@5488.5,2285.01 C311.1@5488.5,2359 5507.9,2378.41 5507.28,2379.03 U301.5@5507.28,2419
NetC312_1: C312.1 C313.1 R316.1 R317.2 U303.1 | length 376
  Layer 1 - Top Layer w25: C313.1@5800,2036.5 5853.5,2036.5 v1(5873.5,2016.5)
  Layer 1 - Top Layer w30: C312.1@5745,2096.5 5778.5,2096.5 5800,2075 5800,2057.18
  Layer 6 - Bottom Layer w25: U303.1@5747.24,1977.4 5822.4,1977.4 R316.1@5825,1974.8 ; R317.2@5825,1910 R316.1@5825,1974.8 ; v1(5873.5,2016.5) 5837.01,1980 R316.1@5825,1980 R316.1@5825,1974.8
NetC312_2: C312.2 R315.2 | length 36.3
  Layer 1 - Top Layer w30: R315.2@5745,1976.5 5745,2012.82
NetC313_2: C313.2 R313.1 R315.1 U302.2 U303.2 | length 1057.9
  Layer 1 - Top Layer w30: v1(5665,1835) R313.1@5665,1915 5743.5,1915 R315.1@5745,1913.5 5763.5,1913.5 5800,1950 5800,1952.82
  Layer 6 - Bottom Layer w30: U303.2@5747.24,1902.6 5732.6,1902.6 v1(5665,1835) 5665,1805 5735,1735 6040,1735 6080,1695 6080,1570 6030,1520 U302.2@6002.17,1520
NetC319_1: C319.1 D306.2 R302.1 U304.9 | length 204.4
  Layer 6 - Bottom Layer w10: D306.2@3279.47,1100 3348.5,1100 R302.1@3350,1101.5 3374,1125.5 3375.15,1125.5 3395,1145.35 C319.1@3415.65,1145.35 U304.9@3465.04,1145.35
NetD100_1: D100.1 R100.2 | length 109.5
  Layer 6 - Bottom Layer w25: D100.1@2951.48,1764 2960,1772.52 R100.2@2960,1870
NetD101_1: D101.1 R103.2 | length 111.5
  Layer 6 - Bottom Layer w25: R103.2@2675,2065 2678.74,2061.26 D101.1@2678.74,1955
NetD102_1: D102.1 K100.1 Q100.3
NetD102_2: D102.2 K100.5 R106.1 R107.1
NetD106_2: D106.2 R114.1 | length 115.3
  Layer 1 - Top Layer w30: D106.2@2155.74,1513 R114.1@2271,1513
NetD107_1: D107.1 R119.1 | length 157.8
  Layer 6 - Bottom Layer w25: D107.1@1396.26,885 1396.26,947.26 1407,958 1428,958 R119.1@1470,1000
NetD107_2: D107.2 Q1.1 R109.1
NetD108_1: D108.1 R120.1 | length 184.3
  Layer 6 - Bottom Layer w50: R120.1@2165,940 2266.26,940 D108.1@2325,998.74
NetD108_2: D108.2 Q2.1 R110.1
NetD300_2: D300.2 R307.2 R308.2 T300.10 | length 1412.2
  Layer 1 - Top Layer w25: R307.2@5151.5,2235 5886.87,2235 T300.10@5937.48,2285.61
  Layer 6 - Bottom Layer w25: R308.2@5415,2343.5 5415,2280 5460,2235 5932.78,2235 ; D300.2@5933.74,2160 D300.2@5937.48,2163.74
NetD301_1: D301.1 R301.1 | length 68.2
  Layer 1 - Top Layer w25: R301.1@5760,2605 5764,2601 5764,2538.48
NetD301_2: D301.2 Q300.2 T300.9
NetD302_2: D302.2 T300.5 | length 148
  Layer 1 - Top Layer w50: T300.5@6272.52,2686.85 6295.67,2710 6410.89,2710
NetD303_2: D303.2 R307.1 | length 74.8
  Layer 1 - Top Layer w25: D303.2@5080,2306.26 5080,2243.5 R307.1@5088.5,2235
NetD304_2: D304.2 T300.2 | length 188.4
  Layer 1 - Top Layer w50: T300.2@6272.52,2391.57 6427.83,2391.57 D304.2@6451.26,2415
NetD305_1: D305.1 R305.1 | length 87.2
  Layer 1 - Top Layer w25: 3300,3046.28 v1(3300,3070)
  Layer 6 - Bottom Layer w25: R305.1@3300,3006.5 v1(3300,3070)
NetF100_1: F100.1 J100.1 TP109.1 | length 929.9
  Layer 6 - Bottom Layer w10: TP109.1@420,2555 565,2410 565,2210 565,1904.33 J100.1@720,1749.33
NetJ104_1: J104.1 U102.12 | length 1531.9
  Layer 6 - Bottom Layer w10: U102.12@6535,2297.01 6535,2660 6625,2750 7214.75,2750 7277.5,2687.25 7277.5,2412.5 J104.1@7215,2350
NetJ104_3: J104.3 U102.13 | length 1338.4
  Layer 6 - Bottom Layer w10: U102.13@6585,2297.01 6585,2660 6657.5,2732.5 7207.5,2732.5 7260,2680 7260,2495 J104.3@7215,2450
NetJ104_5: J104.5 U102.14 | length 1063.4
  Layer 6 - Bottom Layer w10: U102.14@6635,2297.01 6635,2635 6715,2715 7125,2715 7170,2670 7170,2595 J104.5@7215,2550
NetJ200_3: J200.3 R203.2 | length 1195.2
  Layer 1 - Top Layer w10: J200.3@3901.3,1697.78 4062.3,1858.78 4123.78,1858.78 4167.5,1902.5 4167.5,2052.5 4200,2085 4495,2085 v1(4503.62,2076.38)
  Layer 1 - Top Layer w25: J200.3@3901.3,1556.05 J200.3@3901.3,1706.05
  Layer 6 - Bottom Layer w10: v1(4503.62,2076.38) 4503.62,2092 R203.2@4521.62,2110
  Layer 6 - Bottom Layer w25: J200.3@3901.3,1556.05 J200.3@3901.3,1706.05
NetJ202_9: J202.9 R221.2 | length 1221.5
  Layer 1 - Top Layer w12: J202.9@3730,3015 3780,2965 3850,2965 3880,2935 3880,2895 3950,2825 4175,2825 4515,2485 R221.2@4515,2291.5
NetJ202_10: J202.10 R223.2 | length 937.4
  Layer 1 - Top Layer w12: J202.10@3730,2915 3875,2770 4085,2770 4214.57,2640.43 4214.57,2301.93 R223.2@4215,2301.5
NetL104_1: L104.1 R121.2
NetL300_1: L300.1 U304.1 U304.2 U304.3
NetQ300_1: Q300.1 U301.6 | length 138.6
  Layer 1 - Top Layer w15: U301.6@5507.28,2469 5564.9,2469 5588.85,2492.95 Q300.1@5636,2492.95
NetQ300_3: Q300.3 R311.2 R314.2 | length 83.5
  Layer 1 - Top Layer w25: R311.2@5552.5,2284 5635.95,2284 Q300.3@5636,2284.05
NetR100_1: R100.1 R101.2 | length 54
  Layer 6 - Bottom Layer w25: R100.1@2960,1950 2960,2004
NetR101_1: R101.1 R102.2 | length 1705.8
  Layer 4 - Inner Signal 3 w12: v1(3220,2370) 3765,2370 3815,2320 4245,2320 v1(4365,2200)
  Layer 6 - Bottom Layer w12: R101.1@2960,2110 2960,2156 3174,2370 v1(3220,2370) ; R102.2@4295,2145 4295,2150 4345,2200 v1(4365,2200)
NetR103_1: R103.1 R104.2 | length 100
  Layer 6 - Bottom Layer w25: R103.1@2758.74,2066.26 R104.2@2858.74,2066.26
NetR104_1: R104.1 R105.2 | length 1222.2
  Layer 4 - Inner Signal 3 w12: v1(3217,2410) 3700,2410 v1(3840,2550)
  Layer 6 - Bottom Layer w12: R104.1@2855,2146.26 2943.74,2235 2979.37,2235 3154.37,2410 v1(3217,2410) ; R105.2@3840,2480 v1(3840,2550)
NetR112_1: R112.1 U100.16 | length 85.1
  Layer 6 - Bottom Layer w25: U100.16@2757.01,1190 2757.01,1139.37 R112.1@2781.38,1115
NetR205_1: R205.1 R209.2
NetR206_1: R206.1 R207.2 R208.1 R218.1 U202.1 | length 770.8
  Layer 1 - Top Layer w10: v1(3700,2518.27) 3751.73,2518.27 3875,2395 3875,2325 ; R206.1@3818.62,2325 3875,2325 ; R207.2@3931.38,2245 3931.38,2268.62 3875,2325
  Layer 6 - Bottom Layer w10: R218.1@3517.99,2610 3552.99,2645 3611.5,2645 R208.1@3646.5,2610 3700,2556.5 v1(3700,2518.27) U202.1@3669.13,2487.4
NetR208_2: R208.2 U201.4 | length 136.1
  Layer 6 - Bottom Layer w10: U201.4@3470.31,2554.62 3488.54,2554.62 3493.36,2559.43 3532.94,2559.43 R208.2@3583.5,2610
NetR209_1: R209.1 R211.2 | length 1121.2
  Layer 6 - Bottom Layer w25: R211.2@4152,2407 4205,2407 4237,2375 4237,2320 4289,2268 4790,2268 4863,2195 5040,2195 R209.1@5120,2115
NetR218_2: R218.2 R225.2 U201.3 U202.4 | length 495.4
  Layer 6 - Bottom Layer w10: R218.2@3455,2610 3446.69,2601.69 U201.3@3446.69,2554.62 3394.62,2554.62 3365,2525 3365,2405 3393.5,2376.5 3445,2376.5 3524.76,2376.5 U202.4@3560.87,2412.6
NetR303_1: R303.1 U304.4 | length 55.7
  Layer 6 - Bottom Layer w10: U304.4@3575.28,1145.35 3581.02,1145.35 R303.1@3616.38,1110
NetR304_1: R304.1 U300.7 | length 183.6
  Layer 6 - Bottom Layer w10: R304.1@3265,1843.5 3378.5,1843.5 3392.8,1857.8 U300.7@3392.8,1907.68
NetR308_1: R308.1 R312.2 U301.2 | length 201.3
  Layer 1 - Top Layer w25: U301.2@5292.72,2519 5336,2519 v1(5415,2440)
  Layer 6 - Bottom Layer w30: R308.1@5415,2406.5 v1(5415,2440) 5415,2452.82
NetR309_1: R309.1 R313.2 U302.1 | length 768
  Layer 1 - Top Layer w25: v1(5600,1980) 5615,1995 5632.5,1995
  Layer 1 - Top Layer w30: R313.2@5665,1995 R309.1@5665,2075
  Layer 6 - Bottom Layer w25: v1(5600,1980) 5613.07,1966.93 5613.07,1807.43 5725.5,1695 5935,1695 6002.17,1627.83 U302.1@6002.17,1620
NetU300_2: U300.2 U300.3 | length 25.6
  Layer 6 - Bottom Layer w12: U300.3@3367.2,1742.32 U300.2@3392.8,1742.32
PGND_PFC: C108.2 C109.2 C110.2 C115.2 C119.2 C120.2 C122.2 C129.2 C130.2 C131.2 C132.2 C133.1 C134.2 C135.1 C136.2 C137.2 C138.2 C188.1 C216.1 C217.1 C221.2 C288.1 C300.2 C303.2 C310.2 C311.2 C315.2 C316.2 C317.2 C318.1 C319.2 C323.2 C324.2 C326.2 D103.4 J101.2 J101.3 J101.4 J102.2 J103.1 J103.2 J105.1 J105.2 J105.3 J105.4 J105.5 J105.6 J105.P2 J105.P3 J107.1 J200.6 J201.1 J203.1 NT200.1 Q2.3 Q100.2 R108.2 R215.1 R302.2 R310.1 R312.1 R314.1 R317.1 T300.6 TP102.1 TP103.1 U101.3 U101.5 U301.4 U303.3 U304.5 U304.6 U304.7 U304.8 U304.15 U304.16 U304.17@3520.16,1174.88 | length 2127
  Layer 1 - Top Layer w25: Q100.2@2407.24,1332.4 2474.09,1332.4 C188.1@2480,1326.5 R108.2@2545,1326.5 2641.5,1326.5 v1(2665,1350) ; J200.6@4201.3,1556.05 J200.6@4201.3,1706.05 ; R215.1@4893.62,2590 v1(4940,2590) ; C310.2@5200,2377.91 v1(5241.09,2419) U301.4@5292.72,2419 5352.72,2359 C311.2@5425.5,2359
  Layer 5 - Inner Signal 4 w75: 5125,2650 TP102.1@5125,3000
  Layer 6 - Bottom Layer w25: Q2.3@1832,733 1832,773.5 C115.2@1873.5,815 ; 1873.5,834.7 1873.5,943.5 v1(1895,965) ; U101.3@1952.28,1065 1930,1065 1895,1030 v1(1895,965) ; C119.2@1990,1283.62 v1(2028.62,1283.62) ; C122.2@2020,966.38 1953.66,966.38 U101.5@1952.28,965 v1(1895,965) ; C120.2@2093.62,1130 v1(2140,1130) ; J200.6@4201.3,1556.05 J200.6@4201.3,1706.05 ; R310.1@5185,2419 v1(5241.09,2419) ; v1(5388,2592) 5415,2565 R312.1@5415,2536.5 ; v1(5535,2165) C323.2@5590,2165 ; v1(5605,2050) 5652.76,2002.24 U303.3@5652.76,1940
  other v1: 3366,1371 3396,1371 3426,1371 4916.47,1661.21 4951.47,1661.21 5810,1785 5840,1785 5860,2280 5860,2310
  other v3: 3496.54,1151.26 3543.78,1151.26 3520.16,1174.88 3496.54,1198.5 3543.78,1198.5
  other v5: 5864.96,994.96
PM_CLK: C215.1 D201.3 R219.1 R221.1 U200.9 | length 1164.6
  Layer 1 - Top Layer w12: C215.1@4460,2236.38 4507.13,2236.38 R221.1@4515,2228.5 R219.1@4575,2228.5 4675.91,2228.5 4680,2224.41 D201.3@4680,2222.76 v1(4680,2170)
  Layer 4 - Inner Signal 3 w12: v1(4087.56,1935) 4087.56,1969.56 4211.5,2093.5 4269.5,2093.5 4300.5,2062.5 4358.5,2062.5 4401,2105 4615,2105 v1(4680,2170)
  Layer 6 - Bottom Layer w12: U200.9@3989.17,2036.1 3994.7,2036.1 3996.36,2034.44 4003.92,2034.44 4014.48,2023.88 4014.48,2023.08 4087.56,1950 v1(4087.56,1935)
PM_DATA: C214.1 D202.3 R220.1 R223.1 U200.10 | length 1088.4
  Layer 1 - Top Layer w12: R223.1@4215,2238.5 4218.5,2235 4317.6,2235 4320,2232.6 4322.4,2235 4413.62,2235 C214.1@4415,2236.38 4434.69,2216.69 4434.69,2207.13 4471.82,2170 R220.1@4518.5,2170
  Layer 4 - Inner Signal 3 w12: v1(4045,1935) 4045,1980 4013,2012 4013,2056.64 4106.36,2150 4159.5,2150 4197.5,2188 4339,2188 4355.5,2171.5 4416.56,2171.5 4436.06,2191 v1(4452,2191)
  Layer 6 - Bottom Layer w10: U200.10@3989.17,2016.42 4045,1960.59 v1(4045,1935)
PRI_FAULT: J105.10 U102.4 U200.20 | length 5140.3
  Layer 1 - Top Layer w10: v1(4735,2200) 4877.68,2200 5237.68,1840 5534.64,1840 5654.64,1720 6420,1720 v1(6535,1835) 6560,1860 6740,1860 7080,1520 7080,1405 7215,1270 7340,1270 7380,1230 7380,1051 J105.10@7431,1000
  Layer 3 - Inner Signal 2 w10: v1(3755,1950) 3713,1950 3666,1997 3666,2018.85 3635.5,2049.35 3635.5,2105.15 3649.85,2119.5 3660.85,2119.5 3821.35,2280 4105,2280 4218.5,2166.5 4352.15,2166.5 4373.65,2145 4540,2145 4595,2200 v1(4735,2200)
  Layer 6 - Bottom Layer w10: v1(3755,1950) 3786.42,1981.42 U200.20@3786.42,1990.83
  Layer 6 - Bottom Layer w25: v1(6535,1835) 6563.35,1835 6585,1856.65 U102.4@6585,1922.99
Q1_GATE: R117.2 TP200.1 U200.11 | length 5589.2
  Layer 1 - Top Layer w12: TP200.1@1200,3000 1410,2790 3041,2790 3166,2665 3166,1981 3250,1897 v1(3250,1490)
  Layer 4 - Inner Signal 3 w12: v1(2180,1235) 2995,1235 3045,1285 3090,1285 3175,1370 3175,1415 v1(3250,1490) 3335,1490 3750,1905 3825,1905 3878,1958 v1(4005,1958)
  Layer 6 - Bottom Layer w12: R117.2@2111.24,1235 v1(2180,1235) ; U200.11@3963.58,1990.83 3972.17,1990.83 v1(4005,1958)
Q2_GATE: R118.2 TP201.1 U200.12 | length 5641.2
  Layer 1 - Top Layer w12: TP201.1@1450,3000 1630,2820 3103,2820 3190,2733 3190,2062 3339,1913 v1(3339,1454)
  Layer 4 - Inner Signal 3 w12: v1(2180,1180) 2760,1180 2825,1115 3000,1115 v1(3339,1454) 3760,1875 4020,1875 v1(4040,1895)
  Layer 6 - Bottom Layer w12: R118.2@2093.62,1180 v1(2180,1180) ; U200.12@3943.9,1997 3943.9,1971.1 4020,1895 v1(4040,1895)
RELAY_CTRL: C188.2 Q100.1 R108.1 U200.24 | length 1991.1
  Layer 1 - Top Layer w12: Q100.1@2407.24,1257.6 2474.09,1257.6 C188.2@2480,1263.5 R108.1@2545,1263.5 2753.5,1263.5 2810,1320 3070,1320 v1(3140,1390)
  Layer 4 - Inner Signal 3 w12: v1(3140,1390) 3140,1440 3375,1675 3375,2016 3489,2130 3605,2130 v1(3675,2060)
  Layer 6 - Bottom Layer w12: v1(3675,2060) 3684,2069 3710.67,2069 3714.78,2073.1 3745,2073.1 3745,2074.29 3765.17,2074.29 3766.35,2075.47 U200.24@3760.83,2075.47
RELAY_RESET: R204.1 U200.16 | length 132.6
  Layer 6 - Bottom Layer w12: R204.1@3855,1868.62 3855,1900 3865.16,1910.16 U200.16@3865.16,1990.83 U200.16@3865.16,1997
RESET: C218.1 R222.1 S200.1 U200.7 | length 1497.4
  Layer 1 - Top Layer w12: S200.1@3582.68,3000 3582.68,2932.32 3785,2730 3960,2730 4029.5,2660.5 4029.5,2455 4056,2428.5 4056,2371 4029.5,2344.5 4029.5,2164.44 4065,2128.94 4065,2053.56 4066.5,2052.06 4066.5,2010.12 v1(4065,2008.62)
  Layer 6 - Bottom Layer w12: U200.7@3982,2075.47 U200.7@3989.17,2075.47 4084.09,2075.47 C218.1@4085,2076.38 4085,2031.38 R222.1@4086.38,2030 v1(4065,2008.62)
SCI_RX0: U102.5 U200.23 | length 3414.3
  Layer 1 - Top Layer w10: v1(4740,2117.5) 4935.43,2117.5 5230.43,1822.5 5527.4,1822.5 5647.4,1702.5 6452.5,1702.5 v1(6547.24,1797.24)
  Layer 3 - Inner Signal 2 w10: v1(3690,2030) 3710,2050 3740,2050 3788.38,2001.62 3967.97,2001.62 4095.85,2129.5 4219,2129.5 4231,2117.5 v1(4740,2117.5)
  Layer 6 - Bottom Layer w10: v1(3690,2030) 3697.84,2030 3722.44,2054.6 3754.11,2054.6 3755.3,2055.79 U200.23@3760.83,2055.79
  Layer 6 - Bottom Layer w25: U102.5@6535,1922.99 6535,1887.36 6498.03,1850.39 6498.03,1817.91 6518.7,1797.24 v1(6547.24,1797.24)
SCI_TX0: U102.3 U200.22 | length 3347
  Layer 1 - Top Layer w10: v1(4825,2090) 4920,2090 5205,1805 5510,1805 5635,1680 6480,1680 v1(6635,1835)
  Layer 3 - Inner Signal 2 w12: v1(3725,2020) 3761.88,1983.12 3994.06,1983.12 3994.44,1983.5 4015.56,1983.5 4015.94,1983.12 4090.5,1983.12 4158.26,2050.88 4514.18,2050.88 4553.31,2090 v1(4825,2090)
  Layer 6 - Bottom Layer w12: v1(3725,2020) 3725,2031 3730.1,2036.1 U200.22@3767,2036.1
  Layer 6 - Bottom Layer w25: v1(6635,1835) U102.3@6635,1922.99
SWNODE: J101.1 J205.1 L102.3 | length 684
  Layer 1 - Top Layer w10: 5501.3,1348.78 5501.3,1177.48 5535,1143.78 ; 5535,1130 J101.1@6000,1130
TEMP_SENSING: C200.2 TP208.1 U200.3 | length 4353
  Layer 1 - Top Layer w12: v1(4055,2175) 4055,2305 4100,2350 v1(4100,2665)
  Layer 6 - Bottom Layer w12: TP208.1@475,3000 651,2824 3941,2824 v1(4100,2665) ; U200.3@3983,2154.21 4034.21,2154.21 v1(4055,2175)
VDD: C310.1 D303.1 U301.1 U302.4 | length 1731.8
  Layer 1 - Top Layer w25: C310.1@5167.5,2475 5091.26,2475 D303.1@5080,2463.74 5015.74,2463.74 4990,2438 4990,2210 5074,2126 5541,2126 v1(5566,2101) ; C310.1@5200,2492.09 5200,2528 5241,2569 U301.1@5292.72,2569
  Layer 6 - Bottom Layer w25: v1(5566,2101) 5566,1651.83 5597.83,1620 U302.4@5647.83,1620
VO_FB: C207.1 R211.1 R213.2 U200.40 | length 280.6
  Layer 6 - Bottom Layer w12: R211.1@4143,2315 R211.1@4153,2325
  Layer 6 - Bottom Layer w15: U200.40@3964.9,2219.17 3964.9,2245.4 C207.1@3989,2269.5 4038.5,2269.5 4063,2294 R213.2@4063,2327
  Layer 6 - Bottom Layer w25: R213.2@4063,2327 R211.1@4152,2327
pads on no net: D102.3 FID1.1 FID2.1 FID3.1 H1.1 H2.1 H3.1 H4.1 H5.0 H6.0 H7.0 H8.0 H9.1 H10.0 H11.1 H12.0 J100.MH1 J100.MH2 J105.7 J105.9 J105.11 J105.12 J105.MH1 J105.MH2 J202.1 J202.2 J202.3 J202.4 J202.7 J202.8 L102.2 L102.4 LBL1.0 T300.3 U102.6 U102.7 U102.10 U102.11 U200.19 U201.1 U304.17@3520.16,1174.88 U305.4 U305.5

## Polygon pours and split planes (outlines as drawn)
LLC_AGND on Layer 6 - Bottom Layer "LLC_AGND_L06_P190" (solid, remove dead copper, pour order 190): 6658.94,2361.42 6658.94,2493.94 6695,2530 6845,2530 7010,2695 7065,2695 7065,2500 6930,2365 6926.29,2361.29 6659.61,2361.29
3V3LLC on Layer 6 - Bottom Layer "3V3LLC_L06_P188" (solid, remove dead copper, pour order 188): 6720,2275 6720,2410 6740,2430 6890,2430 6905,2445 6905,2525 7045,2525 7075,2495 7165,2495 7165,2385 6815,2385 6780,2350 6750,2320 6750,2275
NetL300_1 on Layer 6 - Bottom Layer "NETL300_1_L06_P186" (solid, remove dead copper, pour order 186): 3563,1210 3575,1222 3808,1222 3808,1148 3573,1148 3563,1158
